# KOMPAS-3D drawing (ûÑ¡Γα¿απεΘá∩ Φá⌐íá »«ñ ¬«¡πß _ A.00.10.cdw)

Views: Изометрия XYZ 3, Изометрия XYZ, Сверху 4, Сверху, Разрез А-А
Referenced files in C:\Users\s.slezkin\Desktop\Чертежи ЗНП\Раскатчик арок 2\: Центрирующая шайба под конус _ A.00.10.m3d, Центрирующая шайба под конус _ A.00.10.cdw
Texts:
  Центрирующая шайба под конус
  http://vk.com/sergey_krd
  Центрирующая
  шайба под конус
Dimensions and other numbers on the sheet: 30; 25; 12; 14; 2,47; 2:1; 1; 0,04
